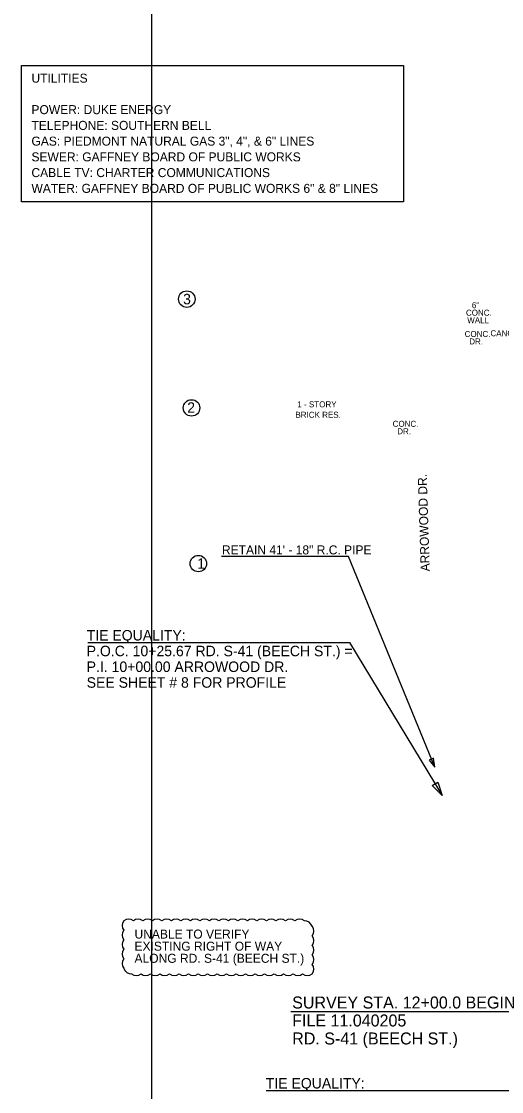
# Model space of a CAD drawing. Extents: x 16382402 to 16388022, y 46194326 to 46202918.
# Drawn here: x 16384265 to 16384585, y 46194799 to 46195513 of the extents above; entities that cross this region are included whole.
import ezdxf

# ---------------------------------------------------------------- set-up
doc = ezdxf.new("R2010")
doc.units = 0
for name, color, linetype in [('RD_EX_DV_Prop', 7, 'Continuous'), ('RD_EX_RW_TX', 7, 'Continuous'), ('RD_EX_SU_TX_Misc', 7, 'Continuous'), ('RD_GPK_Profile_Cell', 7, 'Continuous'), ('RD_HC_Data', 7, 'Continuous'), ('RD_PD_Final_TX', 7, 'Continuous'), ('RD_TX_Bldg', 7, 'Continuous'), ('RD_TX_Drainage', 7, 'Continuous'), ('RD_TX_RoadID', 7, 'Continuous')]:
    doc.layers.add(name, color=color, linetype=linetype)

msp = doc.modelspace()

# ---------------------------------------------------------------- linework, layer by layer
at = {"layer": 'RD_EX_DV_Prop'}
for centre in [(16384374.99, 46195327.45), (16384378.14, 46195254.89), (16384382.71, 46195151.06)]:
    msp.add_circle(centre, 5.49, dxfattribs=at)
at = {"layer": 'RD_EX_RW_TX'}
for centre, radius, start, end in [((16384337.12, 46194909.64), 5.21, 142.5, 217.5), ((16384336.16, 46194908.68), 5.21, 52.5, 127.5), ((16384342.5, 46194908.68), 5.21, 52.5, 127.5), ((16384348.84, 46194908.68), 5.21, 52.5, 127.5), ((16384355.18, 46194908.68), 5.21, 52.5, 127.5), ((16384361.52, 46194908.68), 5.21, 52.5, 127.5), ((16384367.86, 46194908.68), 5.21, 52.5, 127.5), ((16384374.2, 46194908.68), 5.21, 52.5, 127.5), ((16384380.54, 46194908.68), 5.21, 52.5, 127.5), ((16384386.88, 46194908.68), 5.21, 52.5, 127.5), ((16384393.22, 46194908.68), 5.21, 52.5, 127.5), ((16384399.56, 46194908.68), 5.21, 52.5, 127.5), ((16384405.9, 46194908.68), 5.21, 52.5, 127.5), ((16384412.24, 46194908.68), 5.21, 52.5, 127.5), ((16384418.58, 46194908.68), 5.21, 52.5, 127.5), ((16384424.92, 46194908.68), 5.21, 52.5, 127.5), ((16384431.26, 46194908.68), 5.21, 52.5, 127.5), ((16384437.6, 46194908.68), 5.21, 52.5, 127.5), ((16384443.94, 46194908.68), 5.21, 52.5, 127.5), ((16384450.28, 46194908.68), 5.21, 52.5, 127.5), ((16384453.61, 46194907.61), 5.2, 16.78091, 91.78091), ((16384454.46, 46194905.94), 5.21, 322.5, 37.5), ((16384337.12, 46194903.3), 5.21, 142.5, 217.5), ((16384454.46, 46194899.6), 5.21, 322.5, 37.5), ((16384337.12, 46194896.96), 5.21, 142.5, 217.5), ((16384454.46, 46194893.26), 5.21, 322.5, 37.5), ((16384337.12, 46194890.62), 5.21, 142.5, 217.5), ((16384337.12, 46194884.28), 5.21, 142.5, 217.5), ((16384454.46, 46194886.92), 5.21, 322.5, 37.5), ((16384337.97, 46194882.61), 5.2, 196.78091, 271.78091), ((16384454.46, 46194880.58), 5.21, 322.5, 37.5), ((16384341.3, 46194881.54), 5.21, 232.5, 307.5), ((16384347.64, 46194881.54), 5.21, 232.5, 307.5), ((16384353.98, 46194881.54), 5.21, 232.5, 307.5), ((16384360.32, 46194881.54), 5.21, 232.5, 307.5), ((16384366.66, 46194881.54), 5.21, 232.5, 307.5), ((16384373, 46194881.54), 5.21, 232.5, 307.5), ((16384379.34, 46194881.54), 5.21, 232.5, 307.5), ((16384385.68, 46194881.54), 5.21, 232.5, 307.5), ((16384392.02, 46194881.54), 5.21, 232.5, 307.5), ((16384398.36, 46194881.54), 5.21, 232.5, 307.5), ((16384404.7, 46194881.54), 5.21, 232.5, 307.5), ((16384411.04, 46194881.54), 5.21, 232.5, 307.5), ((16384417.38, 46194881.54), 5.21, 232.5, 307.5), ((16384423.72, 46194881.54), 5.21, 232.5, 307.5), ((16384430.06, 46194881.54), 5.21, 232.5, 307.5), ((16384436.4, 46194881.54), 5.21, 232.5, 307.5), ((16384442.74, 46194881.54), 5.21, 232.5, 307.5), ((16384449.08, 46194881.54), 5.21, 232.5, 307.5), ((16384455.42, 46194881.54), 5.21, 232.5, 307.5)]:
    msp.add_arc(centre, radius, start, end, dxfattribs=at)
at = {"layer": 'RD_EX_SU_TX_Misc'}
msp.add_lwpolyline([(16384264.65, 46195483.3), (16384519.46, 46195483.3), (16384519.46, 46195392.4), (16384264.65, 46195392.4)], close=True, dxfattribs=at)
at = {"layer": 'RD_GPK_Profile_Cell'}
msp.add_line((16384351.35, 46195620.8), (16384351.35, 46194370.8), dxfattribs=at)
at = {"layer": 'RD_HC_Data'}
for p, q in [((16384309.01, 46195098.33), (16384483.56, 46195098.33)), ((16384483.56, 46195098.33), (16384545.28, 46194996.46)), ((16384427.9, 46194799.51), (16384669.76, 46194799.51))]:
    msp.add_line(p, q, dxfattribs=at)
at = {"layer": 'RD_PD_Final_TX'}
msp.add_line((16384444.44, 46194852.28), (16384605.01, 46194852.28), dxfattribs=at)
at = {"layer": 'RD_TX_Drainage'}
for p, q in [((16384482.82, 46195155.68), (16384398.19, 46195155.68)), ((16384540.38, 46195015.23), (16384482.82, 46195155.68))]:
    msp.add_line(p, q, dxfattribs=at)
for points in [[(16384536.74, 46195020), (16384540.38, 46195015.23), (16384539.62, 46195021.18)], [(16384542.48, 46195005.31), (16384545.28, 46194996.46), (16384538.65, 46195002.95)]]:
    msp.add_lwpolyline(points, close=True, dxfattribs=at)

# ---------------------------------------------------------------- texts
at = {"layer": 'RD_EX_DV_Prop'}
for s, p in [('3', (16384372.52, 46195323.98)), ('2', (16384375.26, 46195251.62)), ('1', (16384381.96, 46195147.59))]:
    msp.add_text(s, height=7, dxfattribs=at).set_placement(p)
at = {"layer": 'RD_EX_RW_TX'}
for s, p in [('UNABLE TO VERIFY', (16384340.1, 46194900.94)), ('EXISTING RIGHT OF WAY', (16384340.1, 46194892.86)), ('ALONG RD. S-41 (BEECH ST.)', (16384340.1, 46194884.78))]:
    msp.add_text(s, height=6, dxfattribs=at).set_placement(p)
at = {"layer": 'RD_EX_SU_TX_Misc'}
for s, p in [('UTILITIES', (16384271.36, 46195471.83)), ('POWER: DUKE ENERGY', (16384271.36, 46195450.83)), ('TELEPHONE: SOUTHERN BELL', (16384271.36, 46195440.33)), ('GAS: PIEDMONT NATURAL GAS 3", 4", & 6" LINES', (16384271.36, 46195429.83)), ('SEWER: GAFFNEY BOARD OF PUBLIC WORKS', (16384271.36, 46195419.33)), ('CABLE TV: CHARTER COMMUNICATIONS', (16384271.36, 46195408.83)), ('WATER: GAFFNEY BOARD OF PUBLIC WORKS 6" & 8" LINES', (16384271.36, 46195398.33))]:
    msp.add_text(s, height=6, dxfattribs=at).set_placement(p)
at = {"layer": 'RD_HC_Data'}
for s, p in [('TIE EQUALITY:', (16384308.19, 46195099.75)), ('P.O.C. 10+25.67 RD. S-41 (BEECH ST.) =', (16384308.19, 46195089.25)), ('P.I. 10+00.00 ARROWOOD DR.', (16384308.19, 46195078.75)), ('SEE SHEET # 8 FOR PROFILE', (16384308.19, 46195068.25)), ('TIE EQUALITY:', (16384427.64, 46194800.93))]:
    msp.add_text(s, height=7, dxfattribs=at).set_placement(p)
at = {"layer": 'RD_PD_Final_TX'}
for s, p in [('SURVEY STA. 12+00.0 BEGIN', (16384445.3, 46194854.3)), ('FILE 11.040205', (16384445.3, 46194842.3)), ('RD. S-41 (BEECH ST.)', (16384445.3, 46194830.3))]:
    msp.add_text(s, height=8, dxfattribs=at).set_placement(p)
at = {"layer": 'RD_TX_Bldg'}
for s, p in [('6"', (16384565.16, 46195321.39)), ('CONC.', (16384561.21, 46195316.39)), ('WALL', (16384562.05, 46195311.39)), ('CONC.', (16384512.3, 46195242.28)), ('DR.', (16384515.37, 46195237.28))]:
    msp.add_text(s, height=4, rotation=360, dxfattribs=at).set_placement(p)
for s, p in [('CONC.', (16384560.33, 46195302.2)), ('DR.', (16384563.4, 46195297.2)), ('CANOPY', (16384577.55, 46195302.67)), ('1 - STORY', (16384448.75, 46195255.3)), ('BRICK RES.', (16384447.44, 46195248.3))]:
    msp.add_text(s, height=4, dxfattribs=at).set_placement(p)
at = {"layer": 'RD_TX_Drainage'}
msp.add_text('RETAIN 41\' - 18" R.C. PIPE', height=6, dxfattribs=at).set_placement((16384398.42, 46195157.18))
at = {"layer": 'RD_TX_RoadID'}
msp.add_text('ARROWOOD DR.', height=6, rotation=91.79672, dxfattribs=at).set_placement((16384537.08, 46195145.91))

doc.saveas('drawing.dxf')
